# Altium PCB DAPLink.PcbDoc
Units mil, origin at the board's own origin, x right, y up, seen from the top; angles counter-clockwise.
Board outline 3937.01 x 3937.01 mil, 2 copper layers (Top Layer, Bottom Layer); 36 components, 32 nets, 140 pads, 29 vias.
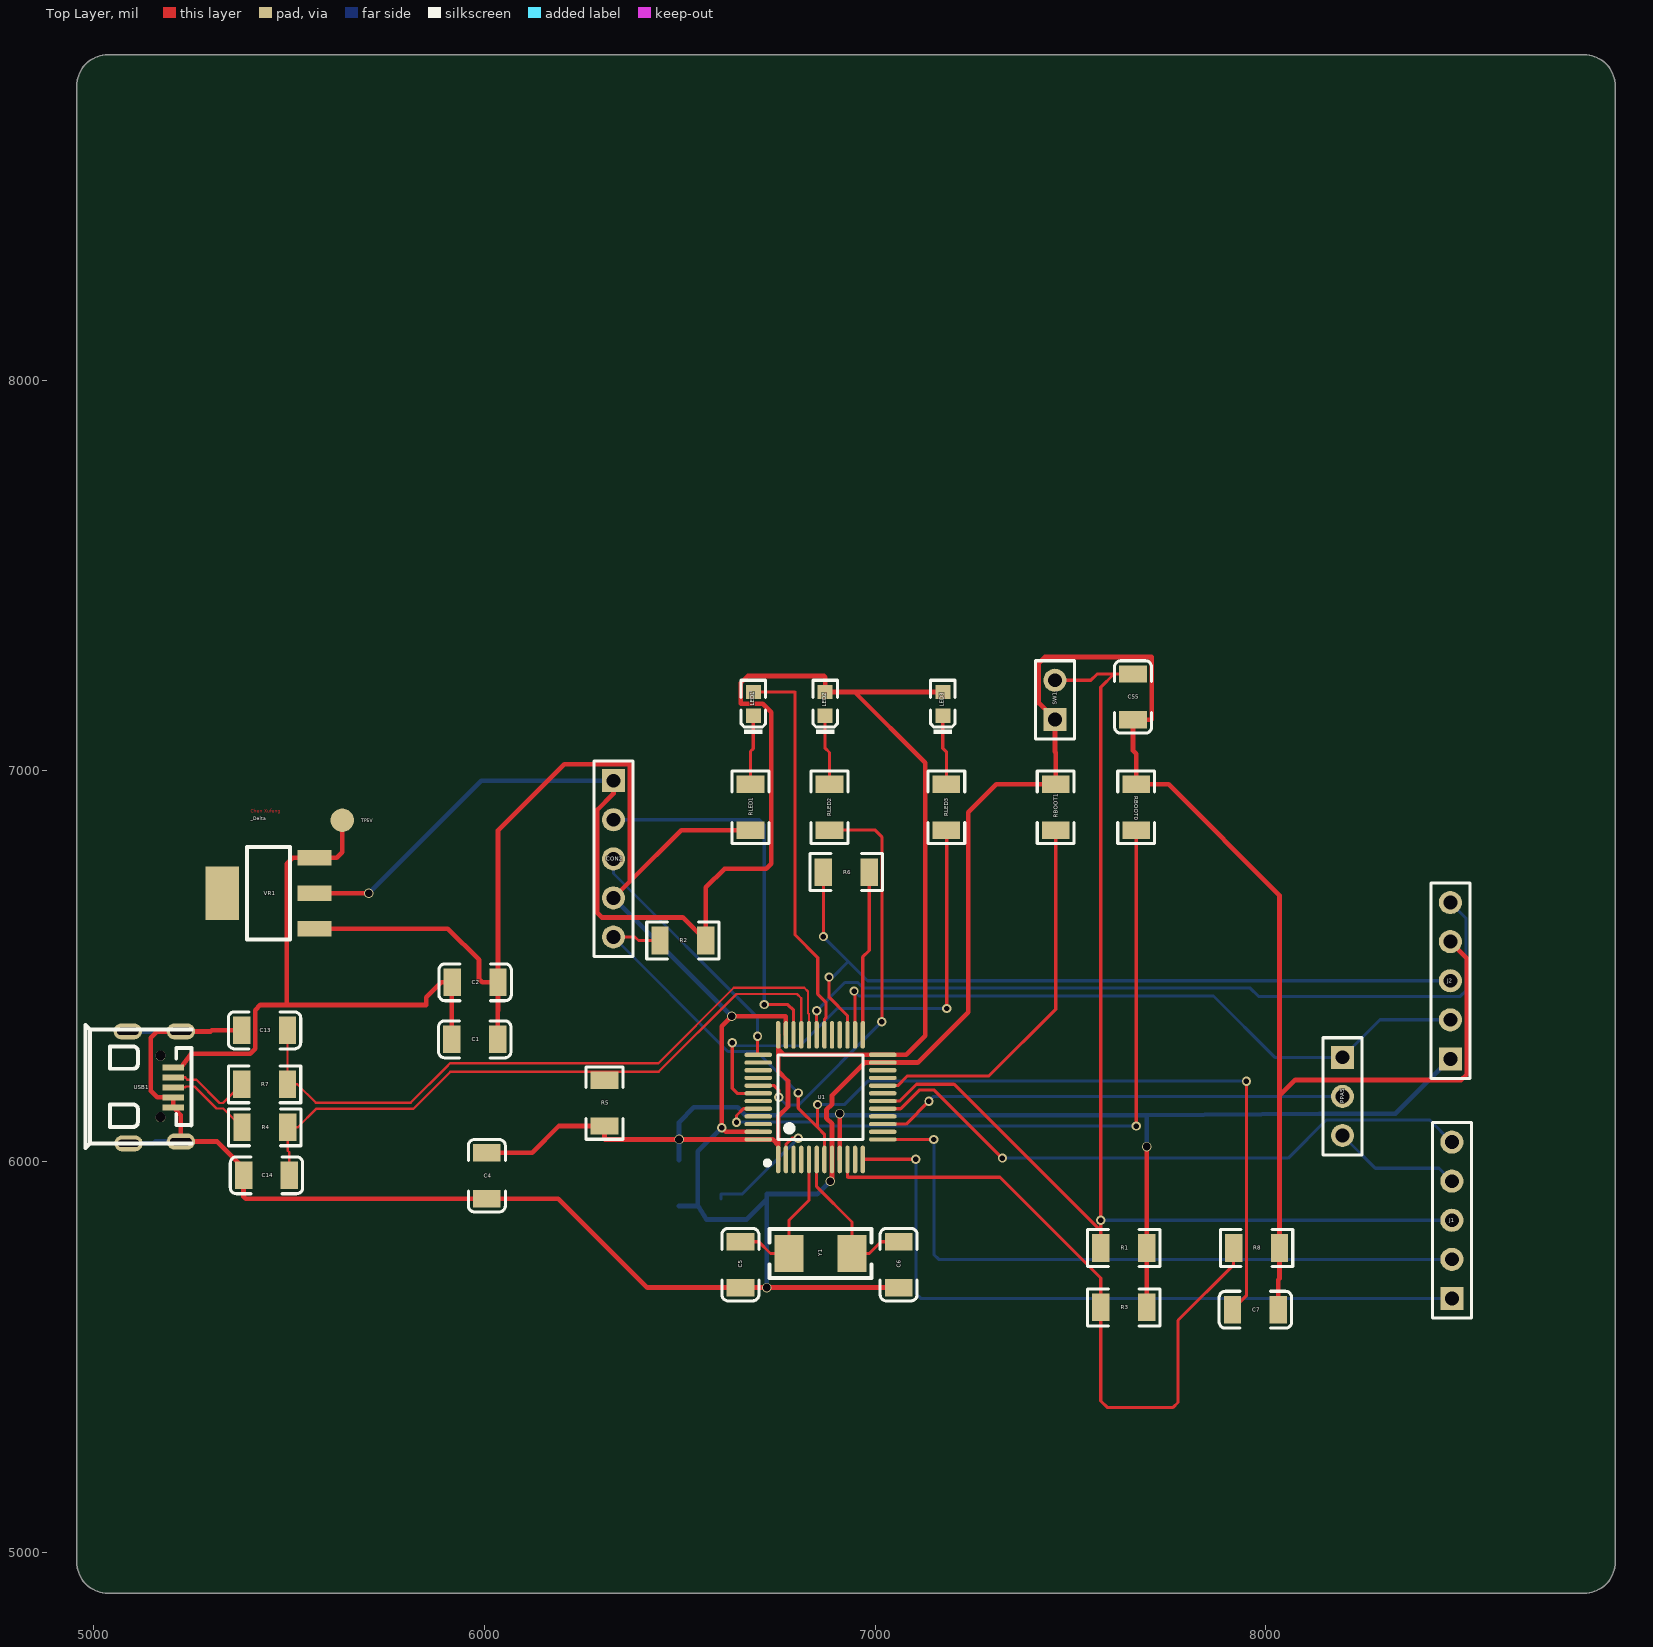
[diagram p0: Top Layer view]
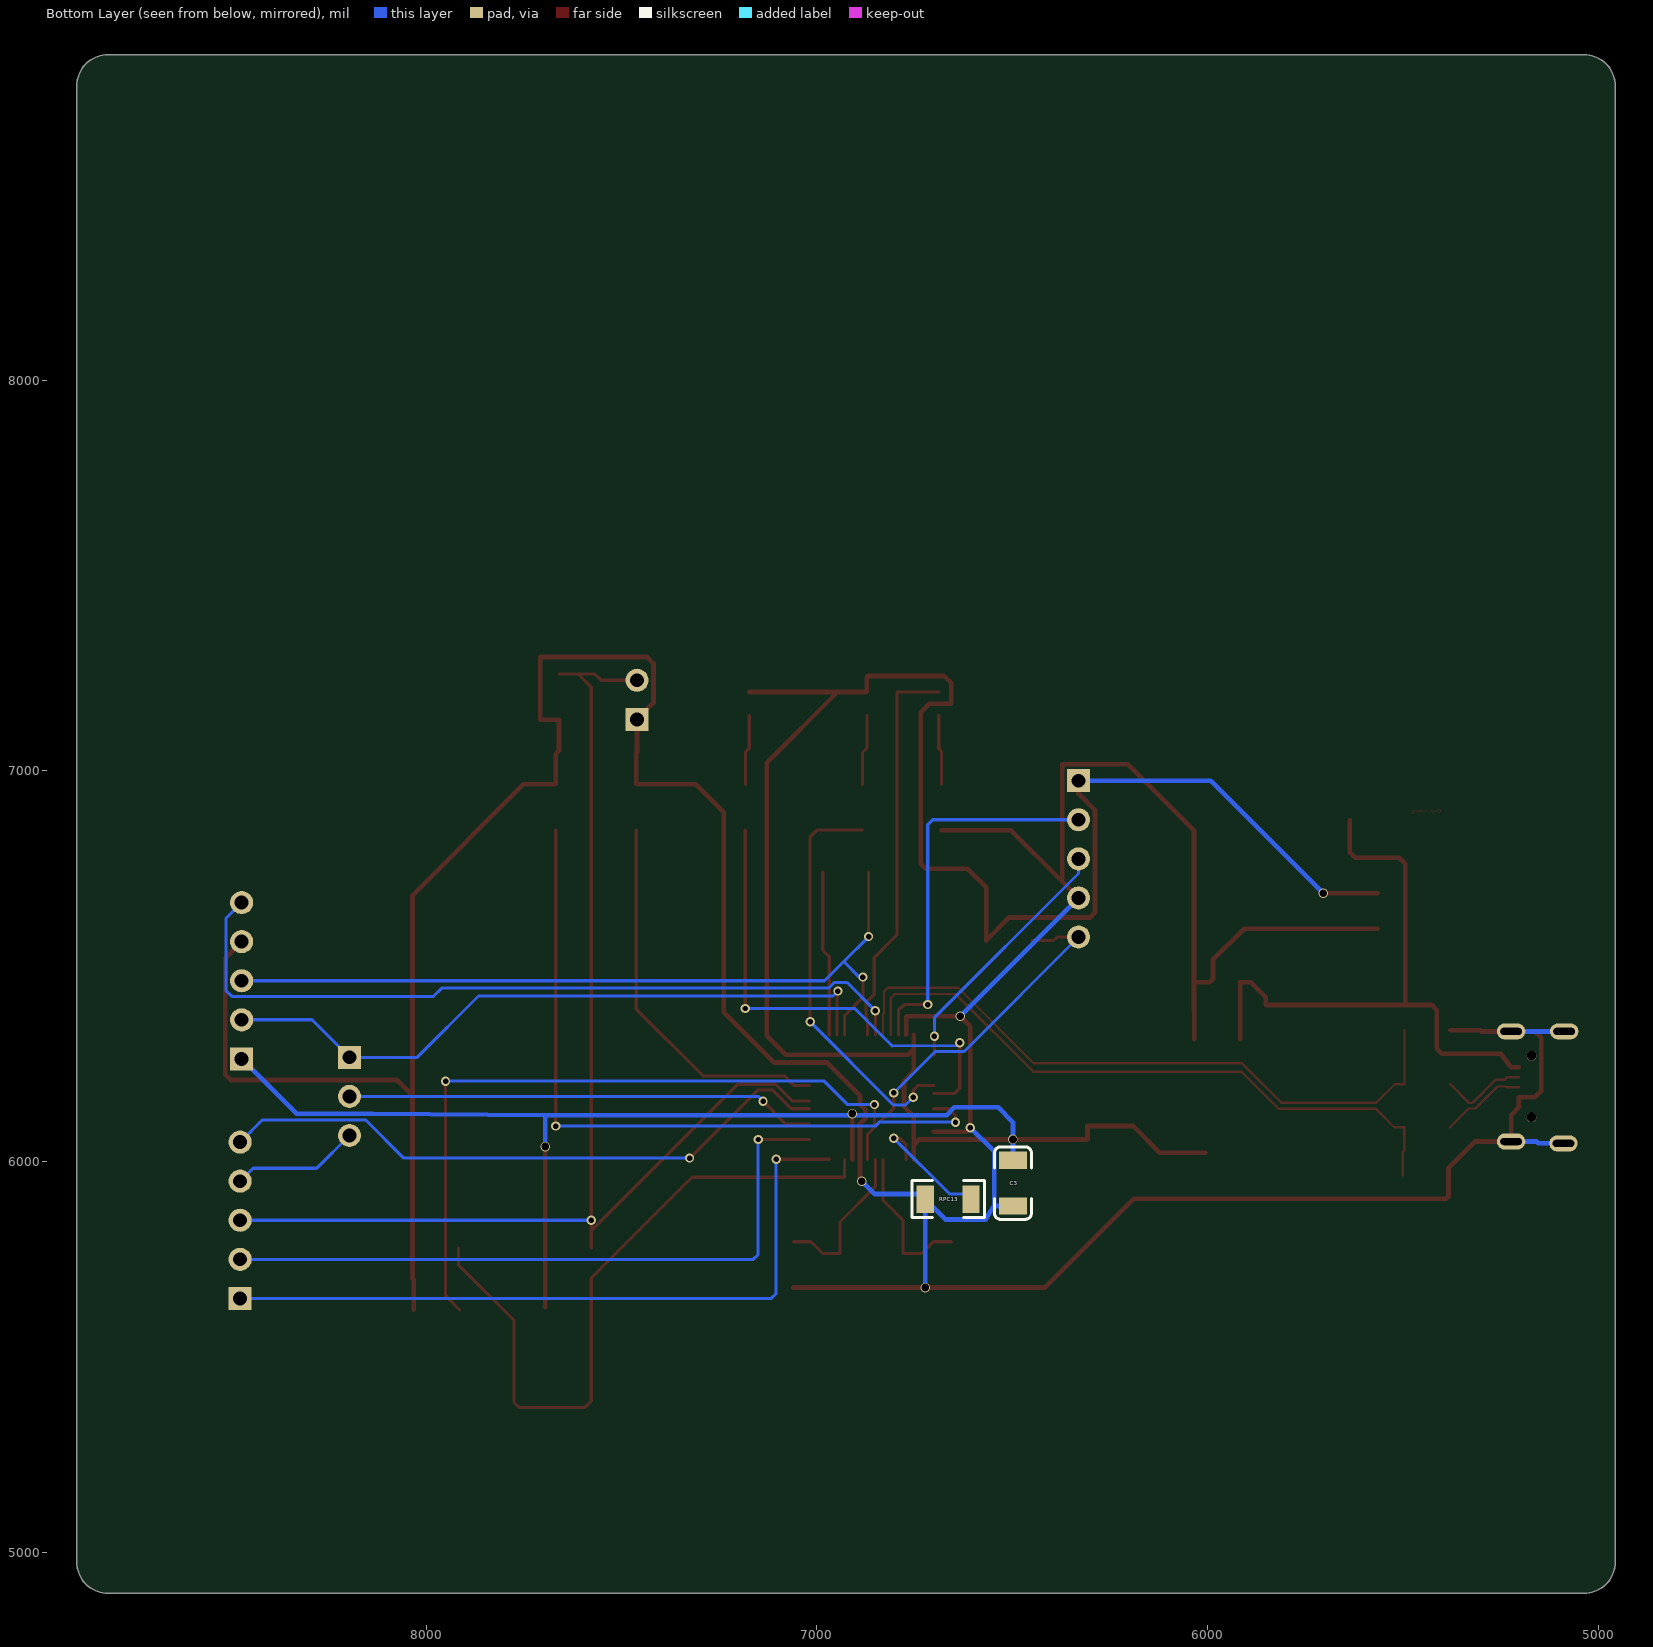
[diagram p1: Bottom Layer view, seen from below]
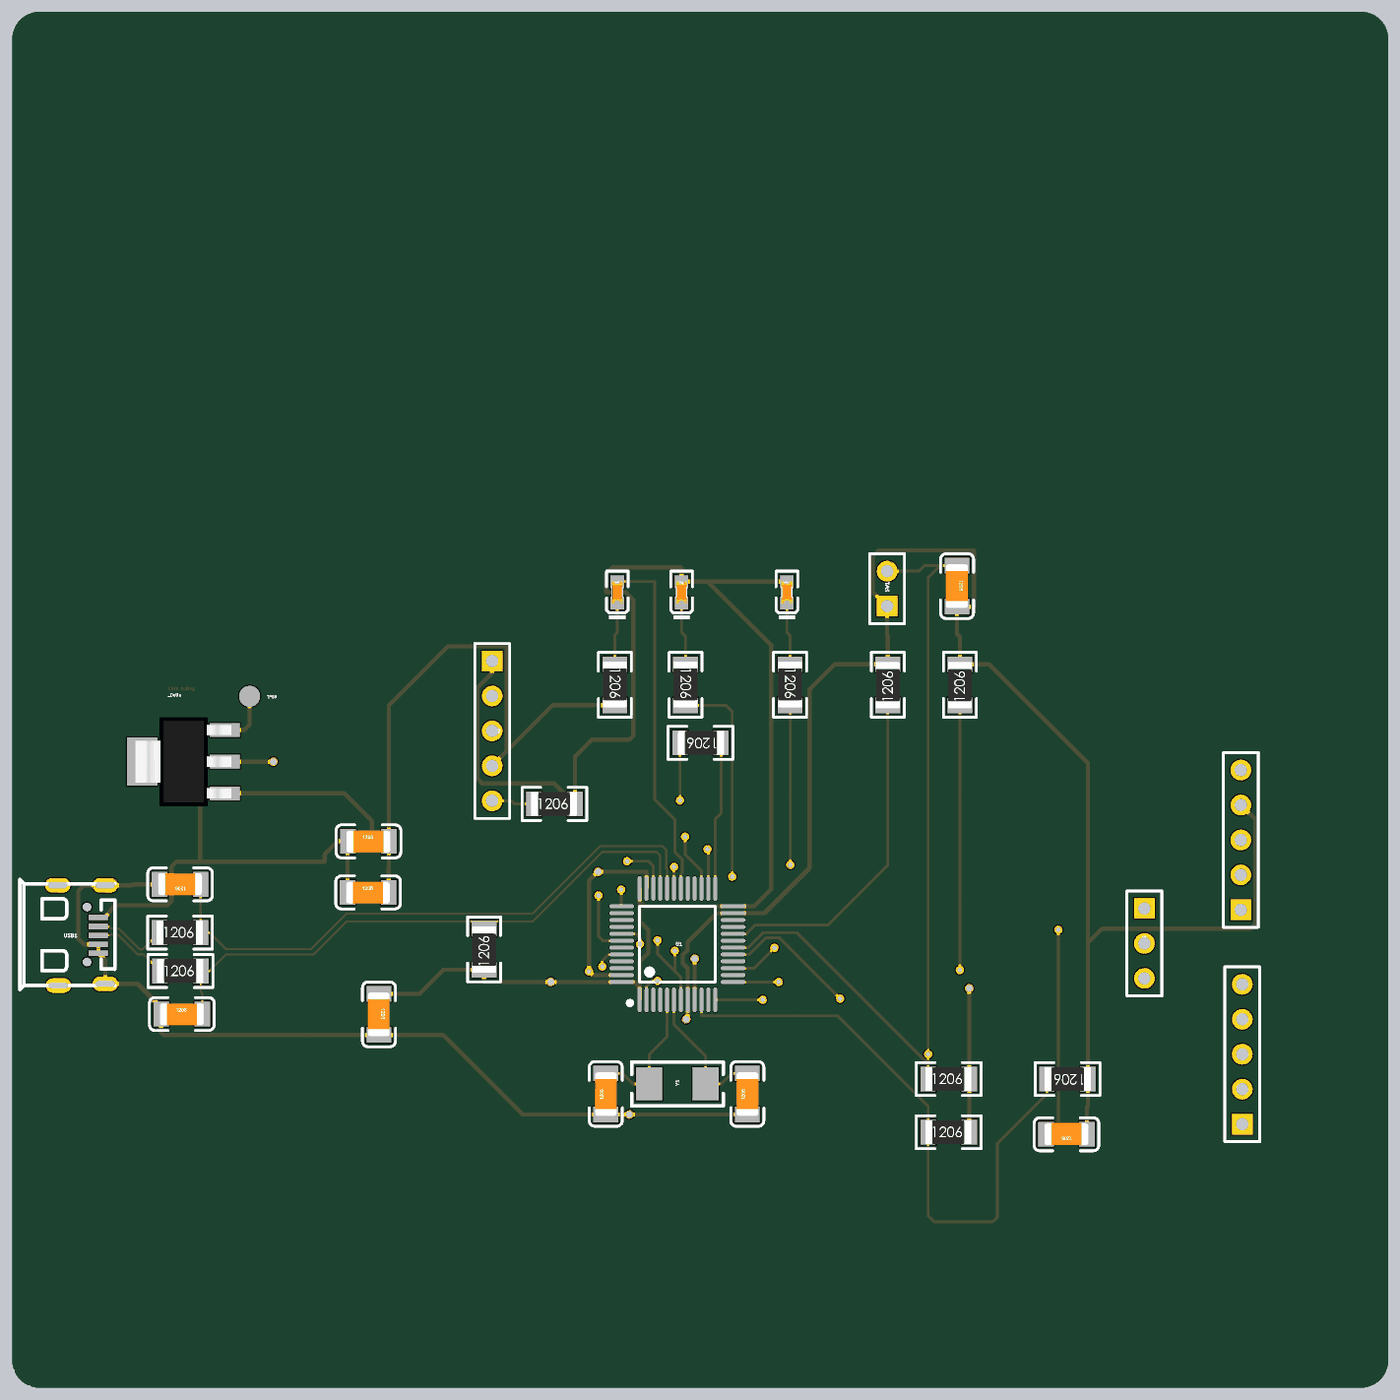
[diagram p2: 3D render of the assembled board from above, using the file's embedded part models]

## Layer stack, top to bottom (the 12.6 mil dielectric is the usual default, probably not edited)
Top Solder: solder mask 0.4, Solder Resist, Dk 3.5
Top Layer: signal copper 1.4
Dielectric 1: dielectric 12.6, FR-4, Dk 4.8
Bottom Layer: signal copper 1.4
Bottom Solder: solder mask 0.4, Solder Resist, Dk 3.5

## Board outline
4956.74,4974.4 ccw(c5035.48,4974.4) 5035.48,4895.66 8815.01,4895.66 ccw(c8815.01,4974.4) 8893.75,4974.4 8893.75,8753.93 ccw(c8815.01,8753.93) 8815.01,8832.67 5035.48,8832.67 ccw(c5035.48,8753.93) 4956.74,8753.93

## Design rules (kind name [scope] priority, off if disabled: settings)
Clearance Polygon [InPolygon] p1: gap=8 ignorepadtopadclearanceinfootprint=FALSE
Clearance [All] p2: gap=6 ignorepadtopadclearanceinfootprint=FALSE
DiffPairsRouting DiffPair_USB1DiffPairsRouting [InDifferentialPair ('TGT_USB_D1')] p1: maxlimit=10 minlimit=10 mostfreqgap=10 toplayer_minwidth=6 toplayer_maxwidth=6 toplayer_prefwidth=6 bottomlayer_minwidth=6 bottomlayer_maxwidth=6 bottomlayer_prefwidth=6 maxuncoupledlength=500
DiffPairsRouting DiffPair_USB0DiffPairsRouting [InDifferentialPair ('TGT_USB_D')] p2: maxlimit=8 minlimit=8 mostfreqgap=8 toplayer_minwidth=6 toplayer_maxwidth=6 toplayer_prefwidth=6 bottomlayer_minwidth=6 bottomlayer_maxwidth=6 bottomlayer_prefwidth=6 maxuncoupledlength=500
DiffPairsRouting [All] p3: maxlimit=10 minlimit=10 mostfreqgap=16 toplayer_minwidth=15 toplayer_maxwidth=15 toplayer_prefwidth=8 bottomlayer_minwidth=15 bottomlayer_maxwidth=15 bottomlayer_prefwidth=8 maxuncoupledlength=500
MatchedLengths DiffPair_USB1MatchedLengths [InDifferentialPair ('TGT_USB_D1')] p1: tolerance=1000 checknetsindiffpair=TRUE checkdiffpairvsdiffpair=FALSE checkxsignals=FALSE checkothers=FALSE
MatchedLengths DiffPair_USB0MatchedLengths [InDifferentialPair ('TGT_USB_D')] p2: tolerance=1000 checknetsindiffpair=TRUE checkdiffpairvsdiffpair=FALSE checkxsignals=FALSE checkothers=FALSE
PolygonConnect Via [IsVia] p1: connectstyle=Direct reliefconductorwidth=10 reliefentries=4 polygonreliefangle="90 Angle" airgapwidth=10
PolygonConnect [All] p2: connectstyle=Relief reliefconductorwidth=10 reliefentries=4 polygonreliefangle="90 Angle" airgapwidth=10
RoutingVias PowerVia [InNetClass('Power')] p1: holewidth=19.68 width=24.41 viastyle="Through Hole" minholewidth=19.68 minwidth=24.41 maxholewidth=19.68 maxwidth=24.41
RoutingVias [All] p2: holewidth=13.78 width=23.62 viastyle="Through Hole" minholewidth=13.78 minwidth=23.62 maxholewidth=13.78 maxwidth=23.62
SolderMaskExpansion [All] p1: expansion=4
Width Power [InNetClass('Power')] p1: maxlimit=60 minlimit=12 preferedwidth=12
Width [All] p2: maxlimit=12 minlimit=6 preferedwidth=8
29 further rules are at their usual default settings.

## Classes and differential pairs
net class Power: GND NetC1_1 VCC33
differential pair TGT_USB_D: +TGT_USB_D_P -TGT_USB_D_N
differential pair TGT_USB_D1: +TGT_USB_D1_P -TGT_USB_D1_N

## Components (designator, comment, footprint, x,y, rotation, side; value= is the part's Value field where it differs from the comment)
C1 "10uF (475) 10% 50V" 1206_C 5975,6313 r0 top
C2 "100nF (475) 10% 50V" 1206_C 5976,6459 r0 top
C3 "10uF (475) 10% 50V" 1206_C 6498,5945 r270 bottom
C4 "100nF (475) 10% 50V" 1206_C 6006,5964 r270 top
C5 "20pF" 1206_C 6655,5736.34 r90 top
C6 "20pF" 1206_C 7060,5736.34 r90 top
C7 "100nF (475) 10% 50V" 1206_C 7973,5621 r180 top
C13 "18pF 10% 50V" 1206_C 5437,6336 r180 top
C14 "18pF 10% 50V" 1206_C 5442,5965 r0 top
C55 "100nF  10% 50V" 1206_C 7660,7189.28 r270 top
CON2 "Header 5" HDR1X5 6330,6975 r270 top
J1 "Header 5" HDR1X5 8476,5650 r90 top
J2 "Header 5" HDR1X5 8472,6263 r90 top
LED1 "红灯 0603" 0603_LED_S1 6688,7171.7 r90 top
LED2 "绿灯 0603" 0603_LED_S1 6871.89,7171.7 r90 top
LED3 "蓝灯 0603" 0603_LED_S1 7173,7171.7 r90 top
PPA5 "Header 3" HDR1X3 8196,6267 r270 top
R1 "100KΩ  ±1%" 1206_R 7636,5779 r0 top
R2 "100KΩ  ±1%" 1206_R 6508,6566 r0 top
R3 "4.7KΩ  ±1%" 1206_R 7636,5627 r0 top
R4 "22Ω  ±1%" 1206_R 5438,6088 r0 top
R5 "10KΩ  ±1%" 1206_R 6307,6150 r90 top
R6 "100Ω  ±1%" 1206_R 6926,6741 r180 top
R7 "22Ω  ±1%" 1206_R 5437,6198 r0 top
R8 "4.7KΩ  ±1%" 1206_R 7976,5779 r180 top
RBOOT0 "100KΩ  ±1%" 1206_R 7668,6907 r90 top
RBOOT1 "100KΩ  ±1%" 1206_R 7462,6907 r90 top
RLED1 "10KΩ  ±1%" 1206_R 6681,6907 r270 top
RLED2 "10KΩ  ±1%" 1206_R 6883,6907 r270 top
RLED3 "10KΩ  ±1%" 1206_R 7182,6907 r270 top
RPC13 "10KΩ  ±1%" 1206_R 6664,5904 r0 bottom
SW1 "Header 2" HDR1X2 7460,7132 r90 top
U1 "STM32F103CBT6" LQFP-48_7x7x05P 6860,6165 r0 top
USB1 "U254-051N-4BH806" MICRO-USB-SMD_U254-051N-4BH806 5155,6190 r270 top
VR1 "AMS1117-3.3" SOT-223 5447,6687 r0 top
Y1 "8MHz 20pF" SMD-5032_2P 6860,5765 r180 top

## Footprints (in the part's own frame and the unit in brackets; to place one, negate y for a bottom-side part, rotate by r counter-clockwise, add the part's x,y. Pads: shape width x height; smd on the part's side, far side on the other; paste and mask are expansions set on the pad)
0603_LED_S1 [mm]
  rect 0.93x0.98 smd: A(0.77,0) K(-0.77,0)
  silkscreen extent -1.97,-0.79 1.54,0.79, body extent -0.8,-0.4 0.8,0.4, height 0.6
1206_C [mm]
  rect 1.13x1.8 smd: 1(-1.49,0) 2(1.49,0)
  silkscreen extent -2.36,-1.2 2.35,1.2, body extent -1.6,-0.81 1.6,0.79, height 1
1206_R [mm]
  rect 1.13x1.8 smd: 1(-1.49,0) 2(1.49,0)
  silkscreen extent -2.35,-1.2 2.35,1.2, body extent -1.7,-0.86 1.65,0.87, height 0.85
HDR1X2 [mm] "Connector; Header; 2 Position"
  rect 1.5x1.5 hole 0.9: 1(0,0)
  round 1.5 hole 0.9: 2(2.54,0)
  silkscreen extent -1.27,-1.27 3.81,1.27
HDR1X3 [mm] "Connector; Header; 3 Position"
  rect 1.5x1.5 hole 0.9: 1(0,0)
  round 1.5 hole 0.9: 2(2.54,0) 3(5.08,0)
  silkscreen extent -1.27,-1.27 6.35,1.27
HDR1X5 [mm] "Connector; Header; 5 Position"
  rect 1.5x1.5 hole 0.9: 1(0,0)
  round 1.5 hole 0.9: 2(2.54,0) 3(5.08,0) 4(7.62,0) 5(10.16,0)
  silkscreen extent -1.27,-1.27 11.43,1.27
LQFP-48_7x7x05P [mm]
  oval 0.28x1.8 smd mask+0.051: 1(-2.75,-4.05) 2(-2.25,-4.05) 3(-1.75,-4.05) 4(-1.25,-4.05) 5(-0.75,-4.05) 6(-0.25,-4.05) 7(0.25,-4.05) 8(0.75,-4.05) 9(1.25,-4.05) 10(1.75,-4.05) 11(2.25,-4.05) 12(2.75,-4.05) 25(2.75,4.05) 26(2.25,4.05) 27(1.75,4.05) 28(1.25,4.05) 29(0.75,4.05) 30(0.25,4.05) 31(-0.25,4.05) 32(-0.75,4.05) 33(-1.25,4.05) 34(-1.75,4.05) 35(-2.25,4.05) 36(-2.75,4.05)
  oval 1.8x0.28 smd mask+0.051: 13(4.05,-2.75) 14(4.05,-2.25) 15(4.05,-1.75) 16(4.05,-1.25) 17(4.05,-0.75) 18(4.05,-0.25) 19(4.05,0.25) 20(4.05,0.75) 21(4.05,1.25) 22(4.05,1.75) 23(4.05,2.25) 24(4.05,2.75) 37(-4.05,2.75) 38(-4.05,2.25) 39(-4.05,1.75) 40(-4.05,1.25) 41(-4.05,0.75) 42(-4.05,0.25) 43(-4.05,-0.25) 44(-4.05,-0.75) 45(-4.05,-1.25) 46(-4.05,-1.75) 47(-4.05,-2.25) 48(-4.05,-2.75)
  silkscreen extent -3.6,-4.42 2.75,2.75
MICRO-USB-SMD_U254-051N-4BH806 [mm]
  rect 0.4x1.4 smd: 1(-1.3,1.225) 2(-0.65,1.225) 3(0,1.225) 4(0.65,1.225) 5(1.3,1.225)
  oval 1.05x1.849 hole 0.45 slot 1.4 at 90 deg: 6(-3.64,1.725) 7(-3.64,-1.725) 8(3.52,1.725) 9(3.64,-1.675)
  round 0.65 hole 0.65 unplated: ""(-2.06,0.405) ""(1.94,0.405)
  silkscreen extent -4.06,-4.48 3.94,2.42
SMD-5032_2P [mm]
  rect 1.9x2.4 smd: 1(-2.05,0) 2(2.05,0)
  silkscreen extent -3.33,-1.6 3.33,1.6
SOT-223 [mm]
  rect 2.2x1 smd: 1(3,-2.3) 2(3,0) 3(3,2.3)
  rect 2.2x3.5 smd: 2(-3,0)
  silkscreen extent -1.4,-3 1.4,3, body extent -3.49,-3.24 3.49,3.24, height 1.64

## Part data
C1 C2 C3 C4 C7 C13 C14 C55: library part "1206 4.7uF (475) 10% 50V", "贴片电容", Package=1206, SuppliersPartNumber=C29823
C5 C6: library part "1206 2.2uF (225) 10% 50V", "贴片电容", Package=1206, SuppliersPartNumber=C12656
CON2 J1 J2: "Header, 5-Pin"
LED1: library part "0603 红灯", "发光二极管", Package=0603, SuppliersPartNumber=C2286
LED2: library part "0603 绿灯", "发光二极管", Package=0603, SuppliersPartNumber=C72043
LED3: library part "0603 蓝灯", "发光二极管", Package=0603, SuppliersPartNumber=C72041
PPA5: "Header, 3-Pin"
R1 R2 R3 R4 R5 R6 R7 R8 RBOOT0 RBOOT1 RLED1 RLED2 RLED3 RPC13: library part "1206 0Ω (0R0) 1%", "贴片电阻", Package=1206, SuppliersPartNumber=C17888
SW1: "Header, 2-Pin"
U1: "ARM", Package=LQFP-48_7x7x05P, SuppliersPartNumber=C8304
USB1: "microUSB", BOM_Manufacturer="XKB Enterprise"
VR1: library part "SOT-223 AMS1117-3.3", "低压差线性稳压(LDO)", Package=SOT-223, SuppliersPartNumber=C6186
Y1: library part "SMD-5032_2P 8MHz 20ppm 20pF", "贴片晶振", Package=SMD-5032_2P, SuppliersPartNumber=C115962

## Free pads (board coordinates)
  round 60 smd: 2(5636,6874)

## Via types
v1: diameter 23.62, hole 13.78, Top Layer to Bottom Layer, 22 vias
v2: diameter 24.41, hole 19.68, Top Layer to Bottom Layer, 7 vias

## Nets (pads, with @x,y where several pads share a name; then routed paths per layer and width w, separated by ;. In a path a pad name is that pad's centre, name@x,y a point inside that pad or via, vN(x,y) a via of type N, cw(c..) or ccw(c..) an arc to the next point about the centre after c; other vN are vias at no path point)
BOOT1: RBOOT1.1 U1.20 | length 981.9
  Top Layer w8: U1.20 7057.93,6194.53 7082.81,6219.4 7291.4,6219.4 7462,6390 RBOOT1.1
GND: C1.2 C2.2 C3.2 C4.2 C5.1 C6.1 C7.1 C13.2 C14.1 C55.2 CON2.4 J2.4 R8.1 RBOOT0.2 RBOOT1.2 RLED1.2 RPC13.2 SW1.1 U1.8 U1.23 U1.35 U1.47 USB1.4 USB1.5 USB1.6 USB1.7 USB1.8 USB1.9 VR1.1 | length 11891.3
  Top Layer w12: C13.2 5301.69,6336 5299,6333.31 USB1.6 5162.5,6333.31 5146,6316.81 5146,6180.91 5162.5,6164.41 USB1.4 USB1.5 5222.91,6119.14 USB1.8 5315.58,6051.42 5383.34,5983.66 C14.1 5383.34,5911 5389,5905.34 C4.2 6188.66,5905.34 6416.32,5677.68 C5.1 v2(6722.66,5677.68) C6.1 ; VR1.1 5906,6596.45 5986,6516.45 5986,6467 5994,6459 C2.2 ; C1.2 6033.66,6385 6034.66,6386 C2.2 ; CON2.4 6372,6717 ; RLED1.2 6503.34,6848.34 6372,6717 ; U1.47 6617.58,6076.42 v1(6607,6087) 6607,6346 v2(6633,6372) 6770.42,6372 6771.42,6371 U1.35 ; v2(6885,5950) 6885,5951.47 6889.53,5956 U1.8 6889.53,6096.86 6875.19,6111.2 6875.19,6132.86 6889.53,6147.2 6889.53,6170.11 6973,6253.58 U1.23 7109,6253.58 7238,6382.58 7238,6894 7309.66,6965.66 RBOOT1.2 7462,7047 7460,7049 SW1.1 7418,7174 7418,7275 7434.5,7291.5 7707,7291.5 7708,7290.5 7708,7131.62 7707,7130.62 C55.2 7660,7052 7668,7044 RBOOT0.2 7751,6965.66 8034.66,6682 8034.66,6168.66 ; C7.1 8031.66,5698 8034.66,5701 R8.1 8034.66,6168.66 ; J2.4 8514,6521 8514,6223 8500,6209 8075,6209 8034.66,6168.66 ; C2.2 6034.66,6847.66 6204,7017 6371,7017 6372,7016 6372,6717
  Bottom Layer w12: USB1.7 USB1.6 ; USB1.9 5153,6046.7 5157.72,6051.42 USB1.8 ; CON2.4 v2(6633,6372) ; v1(6607,6087) 6546,6026 6546,5887.34 ; v2(6722.66,5677.68) RPC13.2 ; v2(6885,5950) 6852,5917 6722.66,5917 RPC13.2 ; 6546,5887.34 C3.2 6545,5886.34 6546,5887.34 ; 6546,5887.34 6568,5852 6670.66,5852 RPC13.2
IF_NRESET: C7.2 CON2.5 R2.1 U1.7 | length 2740
  Top Layer w8: CON2.5 6385,6575 6394,6566 R2.1 ; v1(6803,6175.84) 6803,6137.04 6852.5,6087.54 ; v1(6852.5,6146) 6852.5,6087.54 ; U1.7 6869.84,6070.2 6852.5,6087.54 ; C7.2 7950,5656.66 v1(7950,6206)
  Bottom Layer w8: CON2.5 6623,6282 6696.84,6282 v1(6803,6175.84) ; v1(6852.5,6146) 6921,6146 6981,6206 v1(7950,6206)
IF_SWCLK: CON2.3 U1.37 | length 656.1
  Top Layer w8: v1(6699,6321) 6699,6273.27 U1.37
  Bottom Layer w8: CON2.3 6330,6737.5 6699,6368.5 v1(6699,6321)
IF_SWDIO: CON2.2 U1.34 | length 995.8
  Top Layer w8: v1(6716,6402) 6776.6,6402 6791.1,6387.5 U1.34
  Bottom Layer w8: CON2.2 6703.5,6875 6716,6862.5 v1(6716,6402)
LED_COM_GRN: RLED2.2 U1.41 | length 1050.2
  Top Layer w8: U1.41 6741.46,6194.53 6753,6182.99 v1(6753,6165) ; RLED2.2 7000,6848.34 7017,6831.34 v1(7017,6357.91)
  Bottom Layer w8: v1(6753,6165) 6773,6145 6804.09,6145 v1(7017,6357.91)
LED_DAP_BULE: RLED3.2 U1.42 | length 1241.4
  Top Layer w8: v1(6634,6304) 6634,6187.5 6646.66,6174.84 U1.42 ; RLED3.2 7183,6848.34 v1(7183,6392)
  Bottom Layer w8: v1(6634,6304) 6634,6297 6806.81,6296 6902.81,6392 v1(7183,6392)
LED_PWR_RED: LED1.A U1.30 | length 1018.8
  Top Layer w8: LED1.A 6794.98,7202.02 6795,6580 6853,6522 6853,6428.62 6873.81,6407.81 6873.81,6367.87 6869.84,6363.9 U1.30
NetC1_1: C1.1 C2.1 pad.2 USB1.1 VR1.3 | length 1616.9
  Top Layer w12: USB1.1 5223,6241.18 5249,6276 5400,6276 5413,6289 5413,6387.5 5426.5,6401 5851,6401 5851,6421 5889,6459 C2.1 5916.34,6458 C1.1 ; 5494,6405 5494,6762.5 5509.05,6777.55 VR1.3 5621.55,6777.55 5636,6792 pad.2
NetLED1_K: LED1.K RLED1.1 | length 178.6
  Top Layer w8: RLED1.1 6681,7050 6688,7057 LED1.K
NetLED2_K: LED2.K RLED2.1 | length 180.3
  Top Layer w8: LED2.K 6871.89,7058.11 6883,7047 RLED2.1
NetLED3_K: LED3.K RLED3.1 | length 179.5
  Top Layer w8: LED3.K 7173,7058 7182,7049 RLED3.1
NetR6_1: R6.1 U1.25 | length 423.3
  Top Layer w8: U1.25 6968.27,6524 6984.66,6540.39 R6.1
NetRBOOT0_1: RBOOT0.1 U1.44 | length 1864.3
  Top Layer w8: v1(6645,6101) 6645,6117.97 6662.5,6135.47 U1.44 ; v1(7668,6091) RBOOT0.1
  Bottom Layer w8: v1(6645,6101) 6840,6101 6850,6091 v1(7668,6091)
PA0: R3.1 R8.2 U1.10 | length 1778.9
  Top Layer w8: U1.10 6928.9,5961 6929.9,5960 7319.34,5960 7577.34,5702 R3.1 7577.34,5387.5 7593.84,5371 7762.5,5371 7775,5383.5 7775,5593.66 7917.34,5736 R8.2
PA5: PPA5.2 U1.15 | length 1205.9
  Top Layer w8: U1.15 7079,6096.1 v1(7137.4,6154.5)
  Bottom Layer w8: v1(7137.4,6154.5) 7149.9,6167 PPA5.2
PC13: RPC13.1 U1.2 | length 346.5
  Top Layer w8: U1.2 6771.42,6043.92 6787.5,6060 v1(6803,6060)
  Bottom Layer w8: RPC13.1 6605.34,5917 6660,5917 v1(6803,6060)
PIN_5: C5.2 U1.5 Y1.2 | length 398.5
  Top Layer w8: C5.2 6702,5795 6732,5765 Y1.2 6779.29,5850 6830.47,5901.18 U1.5
PIN_6: C6.2 U1.6 Y1.1 | length 409.8
  Top Layer w8: U1.6 6850.16,5936 6940.71,5845.45 Y1.1 6985,5765 7015,5795 C6.2
TDI: J1.5 U1.17 | length 1612.2
  Top Layer w8: U1.17 7065,6135.47 7112.6,6183.07 7151.43,6183.07 v1(7325.5,6009)
  Bottom Layer w8: v1(7325.5,6009) 8057,6009 8154.53,6106.53 8419.47,6106.53 J1.5
TDO: J1.4 PPA5.3 | length 328.5
  Bottom Layer w8: PPA5.3 8280,5983 8443,5983 J1.4
TGT_NRESET: C55.1 J1.3 R1.1 SW1.2 U1.18 | length 3319.3
  Top Layer w8: U1.18 7062.66,6155.16 7105.57,6198.07 7201.93,6198.07 7577.34,5822.66 ; SW1.2 7552,7232 7567.95,7247.95 7611,7247.95 ; R1.1 7577.34,5822.66 ; C55.1 7611,7247.95 ; 7577.34,5822.66 v1(7577.34,5850) 7577.34,7214.28 7611,7247.95
  Bottom Layer w8: v1(7577.34,5850) J1.3
TGT_RX: J1.1 U1.12 | length 1856.9
  Top Layer w8: U1.12 6968.27,6006 v1(7104,6006)
  Bottom Layer w8: v1(7104,6006) 7104,5662.5 7116.5,5650 J1.1
TGT_SWCLK: J2.2 PPA5.1 U1.26 | length 1749.1
  Top Layer w8: v1(6946,6436.5) 6948.58,6433.92 U1.26
  Bottom Layer w8: v1(6946,6436.5) 6958.5,6424 7866,6424 8023,6267 PPA5.1 8292,6363 J2.2
TGT_SWDIO: J2.3 R6.2 U1.27 | length 2049.4
  Top Layer w8: v1(6867.34,6575.97) R6.2 ; v1(6882,6472.31) 6882,6420.9 6928.9,6374 U1.27
  Bottom Layer w8: v1(6867.34,6575.97) 6931.16,6512.16 ; v1(6882,6472.31) 6891.31,6472.31 6931.16,6512.16 ; J2.3 6980.31,6463 6931.16,6512.16
TGT_SWO: J2.5 U1.31 | length 2016
  Top Layer w8: U1.31 v1(6850.16,6386)
  Bottom Layer w8: v1(6850.16,6386) 6922.47,6458.31 6955.69,6458.31 6970,6444 7960,6444 7981,6423 8497.5,6423 8512,6437.5 8512,6623 J2.5
TGT_TX: J1.2 U1.13 | length 1756
  Top Layer w8: U1.13 v1(7150,6056.73)
  Bottom Layer w8: v1(7150,6056.73) 7150,5762.5 7162.5,5750 J1.2
TGT_USB_D1_N: C13.1 R7.2 U1.32 | length 1727.7
  Top Layer w6: C13.1 R7.2 5520.91,6198 5567.91,6151 5811,6151 5901.31,6241.31 5912,6252 6445,6252 6638,6445 6800,6445 6818.63,6445 6828,6435.63 6828,6380 6830.47,6377.53 U1.32
TGT_USB_D1_P: C14.2 R4.2 R5.2 U1.33 | length 1766.3
  Top Layer w6: C14.2 5500.66,6024 5496.66,6028 R4.2 5521.91,6088 5568.91,6135 5817.63,6135 5912.63,6230 6445.63,6230 6644.63,6429 6800,6429 6810.79,6418.21 U1.33 6810.79,6412.5
TGT_USB_D_N: R7.1 USB1.2 | length 222.2
  Top Layer w6: USB1.2 5233.79,6215.59 5239.38,6210 5262,6210 5322,6150 5330.34,6150 R7.1
TGT_USB_D_P: R4.1 USB1.3 | length 220.2
  Top Layer w6: USB1.3 5233.79,6190 5236,6192.2 5258,6192.2 5314.2,6136 5331.34,6136 R4.1
VCC33: C3.1 C4.1 CON2.1 J2.1 LED2.A LED3.A R1.2 R2.2 R3.2 R5.1 U1.1 U1.9 U1.24 U1.36 U1.48 VR1.2@5565.11,6687 | length 9030.4
  Top Layer w12: VR1.2@5565.11,6687 v2(5704,6687) ; C4.1 6122,6022.66 6190.68,6091.34 R5.1 6307,6057.73 6308,6056.73 v2(6498,6056.73) U1.48 6737.5,6056.73 6751.73,6042.5 ; CON2.1 6330,6942 6288,6900 6288,6637.5 6300.5,6625 6507.66,6625 R2.2 6566.66,6702.16 6614.5,6750 6721.5,6750 6734,6762.5 6734,7150.21 6712.5,7171.71 6657,7171.71 6656,7172.71 6656,7225 6674,7243 6869,7243 6871.89,7240.11 LED2.A 6947,7202.02 ; U1.1 6751.73,6042.5 ; U1.36 6751.73,6287.5 ; U1.9 v2(6909.21,6123) ; LED3.A 6947,7202.02 ; R3.2 R1.2 v2(7694.66,6038.66) ; 6751.73,6042.5 6751.73,6115.75 6776.81,6140.83 6776.81,6206.36 6751.73,6231.44 6751.73,6287.5 ; 6751.73,6287.5 6765.96,6273.27 U1.24 7079,6273.27 7128,6322.27 7128,7021.02 6947,7202.02
  Bottom Layer w12: v2(5704,6687) 5992,6975 CON2.1 ; C3.1 v2(6498,6056.73) 6498,6101 6536.04,6139.04 6647.83,6139.04 6667.86,6119 v2@6909.21,6119 ; v2(6909.21,6123) v2@6909.21,6119 ; v2(7694.66,6038.66) 7694.66,6119 ; J2.1 8331.53,6122.53 8136.94,6122.53 7694.66,6119 ; v2@6909.21,6119 7694.66,6119 ; v2@6909.21,6119 7694.66,6119
pads on no net: U1.3 U1.4 U1.11 U1.14 U1.16 U1.19 U1.21 U1.22 U1.28 U1.29 U1.38 U1.39 U1.40 U1.43 U1.45 U1.46 USB1. VR1.2@5328.89,6687

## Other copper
Top Layer:
  text "Chen Xufeng" at 5402,6893 h8

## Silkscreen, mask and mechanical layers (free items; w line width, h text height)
Top Overlay:
  text "_Delta" at 5402,6874 h8
  text "TP5V" at 5684,6869 h8
Mechanical 12:
  circle w0.5: c8696.9,5092.51 r59.06
  circle w0.5: c5153.59,5092.51 r59.06
  circle w0.5: c8696.9,8635.82 r59.06
  circle w0.5: c5153.59,8635.82 r59.06
  lines w0.5: 4956.74,4974.4 ccw(c5035.48,4974.4) 5035.48,4895.66 8815.01,4895.66 ccw(c8815.01,4974.4) 8893.75,4974.4 8893.75,8753.93 ccw(c8815.01,8753.93) 8815.01,8832.67 5035.48,8832.67 ccw(c5035.48,8753.93) 4956.74,8753.93 4956.74,4974.4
